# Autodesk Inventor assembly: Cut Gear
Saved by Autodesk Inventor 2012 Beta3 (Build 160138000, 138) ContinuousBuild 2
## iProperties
Created: 2011-01
Part Number: Cut Gear
Document SubType Name: Assembly
Designer: Beta-8540w
Categories: <?xml version="1.0" encoding="UTF-16"?> <MemberInstance><Categories><FamilyTemplate/><ParamToTemplateMap><ParamToTemplate><ParamToTemplate CategoryParameter="//
ClientObjectVersion: 1
Author: Beta-8540w
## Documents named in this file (1)
- C:\Inventor 2012 Essentials\Assemblies\Chapter 8\Design Accelerators\Cut Gear c08-04.iam
